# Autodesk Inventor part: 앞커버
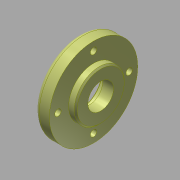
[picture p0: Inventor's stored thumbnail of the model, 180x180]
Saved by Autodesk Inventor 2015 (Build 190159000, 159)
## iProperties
Created: 2015-12
Part Number: 앞커버
Document SubType Name: Modeling
Designer: mdu
Density: 2.71 g/cm^3
Material: 알루미늄 6061
Mass: 70.9292 g
Surface Area: 93.9278 cm^2
Volume: 26.1731 cm^3
Appearance: 알루미늄 - 평지
Author: mdu
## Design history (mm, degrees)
sketch "스케치1"
  geometry: L1 (-7.5, 0)-(7.5, 0); L2 (-7.5, 0)-(-7.5, 31); L3 (-7.5, 31)-(2.5, 31); L4 (2.5, 31)-(2.5, 17.5); L5 (2.5, 17.5)-(7.5, 17.5); L6 (7.5, 17.5)-(7.5, 0); 2 further points
  constraints: 12 end point, 3 perpendicular, 1 coincident, 1 horizontal, 1 midpoint, 1 parallel
  dimensions: "d0" = 15 distance of L1.start L1.end; "d1" = 62 diameter of L3 L1; "d2" = 35 diameter of L5 L1; "d5" = 10 distance of L2.end L3.end
revolve "회전1" sketch "스케치1" stored, may be unused: angle "d6" = 90 deg
sketch "스케치2" dims "d42" = 50
  geometry: 3 further points
  constraints: 2 vertical alignment, 1 coincident, 2 other
hole "구멍1" sketch "스케치2" at (0, 25) diameter "d8" = 4.5; stored, may be unused: countersink angle "d12" = 90 deg, drill point angle "d14" = 118 deg; dims "d9" = 6, "d10" = 8, "d11" = 4.4, "d13" = 8
hole "구멍2" diameter "d20" = 18; stored, may be unused: countersink angle "d24" = 90 deg, drill point angle "d26" = 0 deg; dims "d18" = 10, "d19" = 10, "d21" = 6, "d22" = 8, "d23" = 4.4, "d25" = 8
hole "구멍3" diameter "d34" = 30; stored, may be unused: countersink angle "d38" = 90 deg, drill point angle "d40" = 0 deg; dims "d32" = 10, "d33" = 10, "d35" = 6, "d36" = 4, "d37" = 2, "d39" = 7.3
fillet "모깎기1" dims "d27" = 3, "d41" = 0.3
chamfer "모따기1" distance "d29" = 1; stored, may be unused: second distance "d30" = 2, angle "d31" = 45 deg
node "솔리드1"
pattern_circular "원형 패턴1" dims angle "d16" = 360 deg
